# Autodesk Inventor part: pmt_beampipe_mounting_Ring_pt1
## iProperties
Shininess: 64.0
Length Units: 11269
Angle Units: 11279
Time Units: 11290
Mass Units: 11283
Length Display Precision: 3
Angle Display Precision: 2
Compacted: True
Part Number: pmt_beampipe_mounting_Ring_pt1
Document SubType Name: Modeling
Created: 2004-08
Designer: John Blackburn
Manufacturer: Standard
Standards Organization: Custom
Material: Aluminum-6061
Density: 0.0
Volumn: 0.0
Area: 0.0
PropertySet Name: Model Information
Control State: 0
Master: False
Checked Out: False
Author: John Blackburn
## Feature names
1. Extrusion1
2. Extrusion3
3. Hole1
4. Extrusion4
5. Hole2
6. Extrusion5
7. Split1
8. Extrusion6
9. Extrusion7
10. Hole3
11. Hole6
12. Hole7
